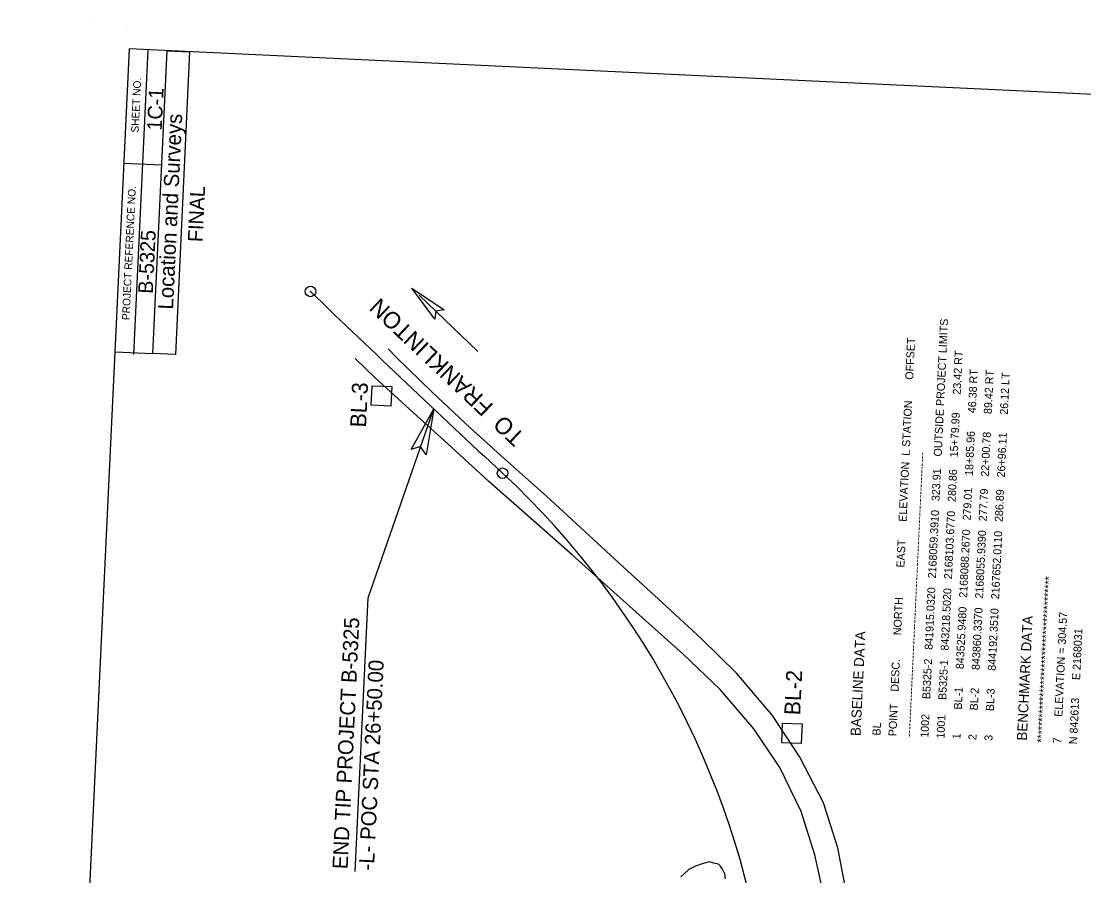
# Model space of a CAD drawing. Extents: x 2167298 to 2168977, y 841960 to 844561.
# Drawn here: x 2167298 to 2168343, y 843720 to 844561 of the extents above; entities that cross this region are included whole.
import ezdxf

# ---------------------------------------------------------------- set-up
doc = ezdxf.new("R2010")
doc.units = 0
for name, color, linetype in [('CTL Sheet Border CELL', 7, 'Continuous'), ('CTL Sheet Text', 7, 'Continuous'), ('CTL Supplemental Horizontal and Vertical CELL', 7, 'Continuous'), ('CTL Supplemental Horizontal and Vertical Text', 7, 'Continuous'), ('Default', 7, 'Continuous'), ('Exist Hydro Stream or Body of Water', 7, 'Continuous'), ('Exist Roads EOP', 7, 'Continuous'), ('Prop Horizontal Alignment', 7, 'Continuous'), ('Typical Terminator CELL', 7, 'Continuous')]:
    doc.layers.add(name, color=color, linetype=linetype)

# ---------------------------------------------------------------- blocks, each defined once
blk = doc.blocks.new('TERMINATOR')
at = {"layer": 'Typical Terminator CELL'}
blk.add_lwpolyline([(-0.469, 0.081), (0, 0), (-0.471, -0.083), (-0.411, 0)], close=True, dxfattribs=at)

msp = doc.modelspace()

# ---------------------------------------------------------------- linework, layer by layer
at = {"layer": 'CTL Sheet Border CELL'}
for p, q in [((2167367.4, 844561.1), (2167367.4, 844561.1)), ((2167400.7, 844552.7), (2167400.7, 844552.7)), ((2167408.3, 844233.2), (2167422.5, 844532.9)), ((2167398.4, 844421.5), (2167435.9, 844419.7)), ((2167389.7, 844235.8), (2167427.1, 844234))]:
    msp.add_line(p, q, dxfattribs=at)
for points in [[(2167403.7, 844533.8), (2167297.5, 842286.3), (2168870.8, 842212), (2168976.9, 844459.5)], [(2167427.1, 844234), (2167441.2, 844532.1), (2167463.2, 844531), (2167449.2, 844233)]]:
    msp.add_lwpolyline(points, close=True, dxfattribs=at)
at = {"layer": 'CTL Supplemental Horizontal and Vertical CELL'}
for p, q in [((2167652, 844192.4), (2167652, 844192.4)), ((2168055.9, 843860.3), (2168055.9, 843860.3))]:
    msp.add_line(p, q, dxfattribs=at)
for points in [[(2167642.9, 844202.4), (2167662.1, 844201.5), (2167661.2, 844182.2), (2167642, 844183.1)], [(2168046.9, 843870.4), (2168066.1, 843869.5), (2168065.2, 843850.2), (2168046, 843851.1)]]:
    msp.add_lwpolyline(points, close=True, dxfattribs=at)
at = {"layer": 'Default'}
for p, q in [((2167746.9, 844236.2), (2167689.1, 844291.5)), ((2167638.8, 843993.6), (2167703.5, 844179.7)), ((2167626.1, 843724.4), (2167638.8, 843993.6))]:
    msp.add_line(p, q, dxfattribs=at)
at = {"layer": 'Exist Hydro Stream or Body of Water'}
msp.add_lwpolyline([(2167990.6, 843717), (2167989.9, 843722), (2167987.8, 843726.7), (2167985.7, 843729.6), (2167983.8, 843731.5), (2167979.3, 843732.7), (2167974.8, 843733.7), (2167968.6, 843732.1), (2167961.1, 843729.5), (2167954.4, 843726.2), (2167950.1, 843721.9), (2167946.8, 843719)], dxfattribs=at)
at = {"layer": 'Exist Roads EOP'}
for points in [[(2168111, 843696.2), (2168101.3, 843747.7), (2168087.1, 843791.9), (2168063.9, 843837), (2168036.9, 843877.7), (2168001.7, 843919.3), (2167966.8, 843953.8), (2167928.4, 843989), (2167894.2, 844020.1), (2167856.4, 844055.1), (2167814.4, 844093.7), (2167776.2, 844127.9), (2167739.2, 844160.8), (2167701.7, 844196.3), (2167666.5, 844230.4), (2167658.5, 844238.6)], [(2168111, 843696.2), (2168101.3, 843747.7), (2168087.1, 843791.9), (2168063.9, 843837), (2168036.9, 843877.7), (2168001.7, 843919.3), (2167966.8, 843953.8), (2167928.4, 843989), (2167894.2, 844020.1), (2167856.4, 844055.1), (2167814.4, 844093.7), (2167776.2, 844127.9), (2167739.2, 844160.8), (2167701.7, 844196.3), (2167666.5, 844230.4), (2167658.5, 844238.6)], [(2168088.6, 843694.7), (2168078.6, 843740.7), (2168065.2, 843783.3), (2168044.1, 843826.6), (2168018.5, 843864.9), (2167985.5, 843903.4), (2167949.1, 843938.3), (2167911.8, 843971.3), (2167877.3, 844002.1), (2167840, 844035.6), (2167796.1, 844074.5), (2167757.6, 844108.3), (2167720.9, 844142), (2167683.1, 844176.1), (2167646, 844210.1), (2167626.2, 844229.2)], [(2168088.6, 843694.7), (2168078.6, 843740.7), (2168065.2, 843783.3), (2168044.1, 843826.6), (2168018.5, 843864.9), (2167985.5, 843903.4), (2167949.1, 843938.3), (2167911.8, 843971.3), (2167877.3, 844002.1), (2167840, 844035.6), (2167796.1, 844074.5), (2167757.6, 844108.3), (2167720.9, 844142), (2167683.1, 844176.1), (2167646, 844210.1), (2167626.2, 844229.2)]]:
    msp.add_lwpolyline(points, dxfattribs=at)
at = {"layer": 'Prop Horizontal Alignment'}
for centre, radius in [((2167582.2, 844295.2), 5.19), ((2167582.2, 844295.2), 0.167), ((2167771.2, 844116.3), 5.19), ((2167771.2, 844116.3), 0.167)]:
    msp.add_circle(centre, radius, dxfattribs=at)
for centre, radius, start, end in [((2177457.8, 854543.7), 14232.4, 226.06143, 227.10916), ((2167204.3, 843506), 833, 7.279, 47.1092)]:
    msp.add_arc(centre, radius, start, end, dxfattribs=at)

# ---------------------------------------------------------------- block references
at = {"layer": 'Default'}
for p, xscale, yscale, rotation in [((2167681.8, 844298.4), 79.99999999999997, 79.99999999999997, 136.269790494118), ((2167703.5, 844179.7), 95.99999999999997, 95.99999999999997, 70.82132466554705)]:
    msp.add_blockref('TERMINATOR', p, dxfattribs=dict(at, xscale=xscale, yscale=yscale, rotation=rotation))

# ---------------------------------------------------------------- texts
at = {"layer": 'CTL Sheet Border CELL'}
for s, height, p in [('SHEET NO.', 7.5, (2167413, 844451.3)), ('1C-1', 14.52, (2167435.7, 844453.2)), ('Location and Surveys', 15, (2167446.9, 844277.1)), ('PROJECT REFERENCE NO.', 7.5, (2167404.1, 844266.8)), ('FINAL', 14.52, (2167475.9, 844343.5)), ('B-5325', 14.52, (2167427, 844292.7))]:
    msp.add_text(s, height=height, rotation=87.2959, dxfattribs=at).set_placement(p)
at = {"layer": 'CTL Sheet Text'}
for s, height, p in [('1002     B5325-2   841915.0320   2168059.3910   323.91    OUTSIDE PROJECT LIMITS                 ', 7.878, (2168190.3, 843855.8)), ('POINT    DESC.        NORTH          EAST      ELEVATION  L STATION       OFFSET', 7.878, (2168158.8, 843857.3)), ('1001     B5325-1   843218.5020   2168103.6770   280.86    15+79.99      23.42 RT', 7.878, (2168206.1, 843855)), ('1        BL-1      843525.9480   2168088.2670   279.01    18+85.96      46.38 RT', 7.878, (2168221.8, 843854.3)), ('2        BL-2      843860.3370   2168055.9390   277.79    22+00.78      89.42 RT', 7.878, (2168237.5, 843853.5)), ('3        BL-3      844192.3510   2167652.0110   286.89    26+96.11      26.12 LT', 7.878, (2168253.3, 843852.8)), ('--------------------------------------------------------------------------------', 7.878, (2168174.6, 843856.5)), ('****************************************', 7.878, (2168305.1, 843850.9)), ('BENCHMARK DATA', 9.847, (2168287.2, 843853)), ('7       ELEVATION = 304.57', 7.878, (2168320.9, 843850.1)), ('BASELINE DATA', 9.847, (2168123.5, 843857.5)), ('N 842613      E 2168031', 7.878, (2168336.6, 843849.4)), ('BL', 7.88, (2168143.1, 843858))]:
    msp.add_text(s, height=height, rotation=87.2959, dxfattribs=at).set_placement(p)
at = {"layer": 'CTL Supplemental Horizontal and Vertical Text'}
for s, p in [('BL-3', (2167636.8, 844161.1)), ('BL-2', (2168064.1, 843877.9))]:
    msp.add_text(s, height=15.69, rotation=87.2959, dxfattribs=at).set_placement(p)
at = {"layer": 'Default'}
for s, height, rotation, p in [('TO  FRANKLINTON', 16.456, 136.5853, (2167794.1, 844153.6)), ('END TIP PROJECT B-5325', 14.96, 87.2959, (2167618.7, 843726.4)), ('-L- POC STA 26+50.00', 14.96, 87.2959, (2167644.6, 843725.1))]:
    msp.add_text(s, height=height, rotation=rotation, dxfattribs=at).set_placement(p)

doc.saveas('drawing.dxf')
